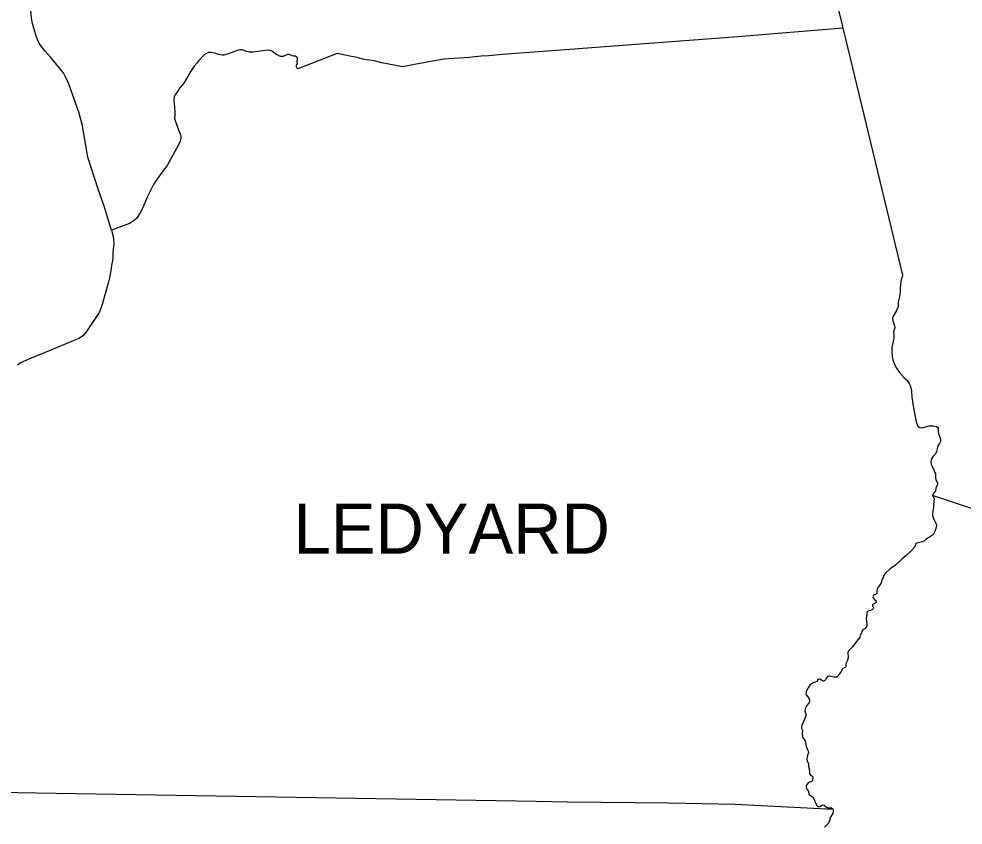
# Model space of a CAD drawing. Extents: x 0 to 2603, y -226 to 830.
# Drawn here: x 309.69 to 335.14, y 553.28 to 575 of the extents above; entities that cross this region are included whole.
import ezdxf

# ---------------------------------------------------------------- set-up
doc = ezdxf.new("R2010")
doc.units = 0
doc.layers.add('CT_TSH_Map_Town_Limits', color=7, linetype='Continuous')
doc.layers.add('CT_TSH_Map_Town_Text', color=7, linetype='Continuous')

msp = doc.modelspace()

# ---------------------------------------------------------------- linework, layer by layer
at = {"layer": 'CT_TSH_Map_Town_Limits'}
for points in [[(331.898, 574.749), (331.892, 574.788), (331.165, 577.753), (330.968, 578.884), (330.872, 579.384), (330.781, 579.888), (330.346, 582.176), (330.166, 583.1), (329.937, 584.312), (329.922, 584.418), (330.537, 584.314), (332.324, 584.014), (332.824, 583.938), (333.334, 583.851), (336.133, 583.399), (337.578, 583.163), (337.811, 583.132), (338.666, 582.985), (340.364, 582.709), (340.772, 582.646), (341.204, 582.573), (341.356, 582.551)], [(312.19, 569.304), (312.12, 569.539), (311.997, 569.924), (311.831, 570.405), (311.546, 571.267), (311.397, 572.164), (311.364, 572.29), (311.313, 572.454), (311.02, 573.295), (310.998, 573.336), (310.943, 573.45), (310.891, 573.542), (310.799, 573.656), (310.552, 573.955), (310.391, 574.139), (310.265, 574.3), (310.202, 574.411), (310.161, 574.53), (310.062, 574.871), (310.038, 574.963), (310.022, 575.107), (309.983, 575.699)], [(331.898, 574.749), (329.066, 574.513), (324.293, 574.151), (322.728, 574.034), (322.36, 574.004), (322.149, 573.99), (321.823, 573.96), (321.141, 573.91), (320.402, 573.777), (320.034, 573.706), (319.801, 573.753), (319.659, 573.777), (319.472, 573.814), (319.262, 573.864), (319, 573.903), (318.807, 573.955), (318.652, 573.987), (318.272, 574.066), (317.208, 573.65), (317.181, 573.675), (317.169, 573.711), (317.172, 573.749), (317.197, 573.789), (317.189, 573.845), (317.204, 573.908), (317.197, 573.945), (317.179, 573.969), (317.137, 573.992), (317.101, 573.996), (317.055, 574.003), (316.985, 574.034), (316.931, 574.034), (316.811, 573.987), (316.755, 573.986), (316.701, 574.004), (316.675, 574.018), (316.639, 574.03), (316.528, 574.118), (316.466, 574.145), (316.403, 574.153), (316.134, 574.118), (316.005, 574.102), (315.904, 574.102), (315.839, 574.118), (315.711, 574.164), (315.638, 574.163), (315.575, 574.145), (315.412, 574.081), (315.211, 574.021), (315.166, 574.018), (315.08, 574.035), (314.969, 574.07), (314.878, 574.087), (314.802, 574.086), (314.747, 574.067), (314.682, 574.024), (314.539, 573.876), (314.484, 573.802), (314.42, 573.723), (314.36, 573.64), (314.322, 573.585), (314.198, 573.371), (314.133, 573.264), (314.032, 573.143), (313.947, 573.013), (313.902, 572.951), (313.878, 572.898), (313.865, 572.799), (313.873, 572.707), (313.888, 572.635), (313.891, 572.476), (313.891, 572.411), (313.889, 572.317), (313.9, 572.261), (313.945, 572.132), (314.004, 571.981), (314.038, 571.903), (314.054, 571.829), (314.056, 571.774), (314.041, 571.702), (314.007, 571.623), (313.684, 571.043), (313.674, 571.018), (313.59, 570.917), (313.543, 570.858), (313.426, 570.693), (313.322, 570.533), (313.153, 570.192), (313.011, 569.869), (312.961, 569.774), (312.862, 569.622), (312.77, 569.545), (312.67, 569.481), (312.457, 569.402), (312.19, 569.304)], [(331.898, 574.749), (331.966, 574.455), (333.501, 568.09), (333.492, 568.043), (333.47, 567.979), (333.455, 567.912), (333.438, 567.739), (333.436, 567.636), (333.426, 567.52), (333.385, 567.373), (333.382, 567.27), (333.373, 567.219), (333.338, 567.141), (333.243, 566.97), (333.233, 566.934), (333.239, 566.869), (333.289, 566.724), (333.292, 566.677), (333.283, 566.649), (333.264, 566.578), (333.266, 566.488), (333.269, 566.398), (333.213, 566.141), (333.212, 566.041), (333.222, 565.898), (333.24, 565.815), (333.294, 565.671), (333.342, 565.584), (333.423, 565.471), (333.561, 565.317), (333.6, 565.283), (333.627, 565.252), (333.685, 565.173), (333.703, 565.135), (333.73, 565.057), (333.741, 564.967), (333.754, 564.805), (333.802, 564.51), (333.875, 564.145), (333.899, 564.066), (333.92, 564.027), (333.952, 563.998), (333.97, 563.987), (334.023, 563.983), (334.217, 564.032), (334.25, 564.038), (334.318, 564.038), (334.416, 564.013), (334.442, 563.994), (334.461, 563.969), (334.467, 563.928), (334.468, 563.876), (334.472, 563.83), (334.522, 563.703), (334.528, 563.636), (334.523, 563.613), (334.498, 563.561), (334.466, 563.512), (334.445, 563.451), (334.419, 563.34), (334.389, 563.283), (334.339, 563.228), (334.328, 563.213), (334.31, 563.193), (334.286, 563.146), (334.267, 563.054), (334.275, 563.003), (334.391, 562.742), (334.395, 562.713), (334.395, 562.622), (334.412, 562.565), (334.447, 562.494), (334.445, 562.455), (334.425, 562.416), (334.407, 562.389), (334.401, 562.353), (334.395, 562.287), (334.376, 562.256), (334.327, 562.202), (334.314, 562.164), (334.314, 562.16)], [(312.19, 569.304), (312.235, 569.137), (312.243, 569.072), (312.252, 568.928), (312.243, 568.863), (312.232, 568.798), (312.222, 568.678), (312.22, 568.552), (312.213, 568.487), (312.191, 568.349), (312.166, 568.212), (312.133, 568.019), (312.097, 567.877), (311.933, 567.299), (311.872, 567.122), (311.839, 567.056), (311.478, 566.523), (311.469, 566.521), (311.413, 566.46), (311.323, 566.392), (311.246, 566.357), (311.155, 566.321), (310.291, 565.964), (310.088, 565.885), (309.881, 565.796), (309.735, 565.733), (309.656, 565.671)], [(334.314, 562.16), (334.352, 562.072), (334.351, 561.995), (334.335, 561.902), (334.334, 561.843), (334.31, 561.678), (334.315, 561.616), (334.35, 561.509), (334.414, 561.394), (334.42, 561.347), (334.405, 561.265), (334.343, 561.121), (334.31, 561.086), (334.226, 561.036), (334.158, 561.003), (334.097, 560.938), (334.043, 560.909), (333.967, 560.888), (333.893, 560.871), (333.859, 560.851), (333.849, 560.826), (333.848, 560.819), (333.833, 560.775), (333.722, 560.653), (333.598, 560.54), (333.491, 560.455), (333.31, 560.283), (333.172, 560.179), (333.034, 560.056), (333.02, 560.041), (332.991, 559.977), (332.948, 559.878), (332.926, 559.807), (332.887, 559.731), (332.836, 559.675), (332.818, 559.639), (332.813, 559.591), (332.812, 559.581), (332.813, 559.528), (332.808, 559.513), (332.794, 559.501), (332.745, 559.481), (332.719, 559.46), (332.705, 559.429), (332.711, 559.403), (332.745, 559.356), (332.795, 559.317), (332.795, 559.293), (332.783, 559.268), (332.751, 559.245), (332.71, 559.226), (332.698, 559.213), (332.694, 559.187), (332.711, 559.148), (332.719, 559.127), (332.712, 559.101), (332.697, 559.087), (332.639, 559.062), (332.592, 559.053), (332.561, 559.03), (332.545, 558.997), (332.538, 558.927), (332.533, 558.913), (332.523, 558.845), (332.533, 558.771), (332.546, 558.703), (332.545, 558.644), (332.527, 558.611), (332.493, 558.579), (332.435, 558.539), (332.41, 558.5), (332.395, 558.451), (332.375, 558.416), (332.354, 558.341), (332.339, 558.311), (332.271, 558.232), (332.158, 558.077), (332.058, 557.979), (332.04, 557.952), (332.034, 557.929), (332.043, 557.787), (332.019, 557.723), (331.981, 557.654), (331.975, 557.61), (331.974, 557.545), (331.969, 557.531), (331.959, 557.521), (331.907, 557.506), (331.887, 557.485), (331.845, 557.398), (331.791, 557.331), (331.76, 557.285), (331.737, 557.268), (331.713, 557.262), (331.659, 557.265), (331.536, 557.29), (331.513, 557.291), (331.485, 557.283), (331.462, 557.252), (331.432, 557.191), (331.402, 557.162)], [(352.196, 556.418), (349.026, 557.372), (346.803, 558.055), (346.503, 558.148), (342.62, 559.406), (342.136, 559.565), (341.106, 559.901), (337.099, 561.235), (334.314, 562.16)], [(331.402, 557.162), (331.373, 557.155), (331.352, 557.158), (331.291, 557.2), (331.266, 557.212), (331.248, 557.214), (331.223, 557.19), (331.195, 557.151), (331.152, 557.132), (331.074, 557.101), (331.016, 557.057), (330.985, 557.022), (330.964, 556.98), (330.923, 556.915), (330.905, 556.862), (330.897, 556.802), (330.904, 556.786), (330.976, 556.694), (330.999, 556.642), (331, 556.605), (330.981, 556.562), (330.917, 556.488), (330.882, 556.413), (330.875, 556.357), (330.893, 556.294), (330.904, 556.259), (330.889, 556.199), (330.792, 555.958), (330.783, 555.93), (330.785, 555.885), (330.806, 555.823), (330.801, 555.742), (330.812, 555.643), (330.822, 555.621), (330.868, 555.57), (330.889, 555.51), (330.896, 555.451), (330.904, 555.398), (330.965, 555.269), (330.969, 555.234), (330.939, 555.164), (330.929, 555.053), (330.935, 554.997), (330.955, 554.961), (330.968, 554.942), (330.97, 554.862), (330.991, 554.803), (330.996, 554.694), (330.995, 554.674), (331.005, 554.647), (331.03, 554.618), (331.074, 554.594), (331.087, 554.568), (331.089, 554.535), (331.066, 554.473), (331.051, 554.455), (330.971, 554.428), (330.925, 554.375), (330.908, 554.339), (330.907, 554.286), (330.925, 554.25), (330.962, 554.206), (330.975, 554.149), (330.981, 554.107), (331.012, 554.081), (331.078, 554.042), (331.095, 554.022), (331.172, 553.841), (331.188, 553.814), (331.226, 553.782), (331.249, 553.775), (331.273, 553.781), (331.318, 553.811), (331.358, 553.824), (331.388, 553.82), (331.454, 553.766), (331.49, 553.745), (331.572, 553.748), (331.587, 553.742), (331.603, 553.735), (331.627, 553.711), (331.631, 553.706)], [(307.359, 554.186), (307.877, 554.188), (308.93, 554.172), (309.658, 554.157), (310.16, 554.149), (323.627, 553.919), (324.469, 553.906), (327.2, 553.877), (328.994, 553.842), (331.631, 553.706)], [(331.631, 553.706), (331.638, 553.655), (331.624, 553.595), (331.576, 553.507), (331.566, 553.494), (331.554, 553.479), (331.549, 553.461), (331.541, 553.418), (331.528, 553.376), (331.505, 553.333), (331.401, 553.223)]]:
    msp.add_lwpolyline(points, dxfattribs=at)

# ---------------------------------------------------------------- texts
at = {"layer": 'CT_TSH_Map_Town_Text'}
msp.add_text('LEDYARD', height=1.35, dxfattribs=at).set_placement((317.093, 560.59))

doc.saveas('drawing.dxf')
